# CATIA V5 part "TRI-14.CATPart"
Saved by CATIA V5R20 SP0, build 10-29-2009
Part number: _TRI-14
Definition: NONE
Nomenclature: _TRI-14
Source: Unknown
Description: PART-_TRI-14-DESC
Bounding box of the stored display mesh (mm): x 0 to 17.5, y -7 to 7, z -7 to 7
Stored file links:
  C:\Users\Utente\Desktop\IO LAVORO\3D X SITO CF\X SITO\PLASTICA\TRI\TRI-14.CATPart
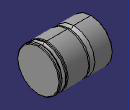
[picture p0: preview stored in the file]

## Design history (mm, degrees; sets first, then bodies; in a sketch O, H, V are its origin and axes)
Body1 "_TRI-14" (main body)
  Solid1: solid without history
